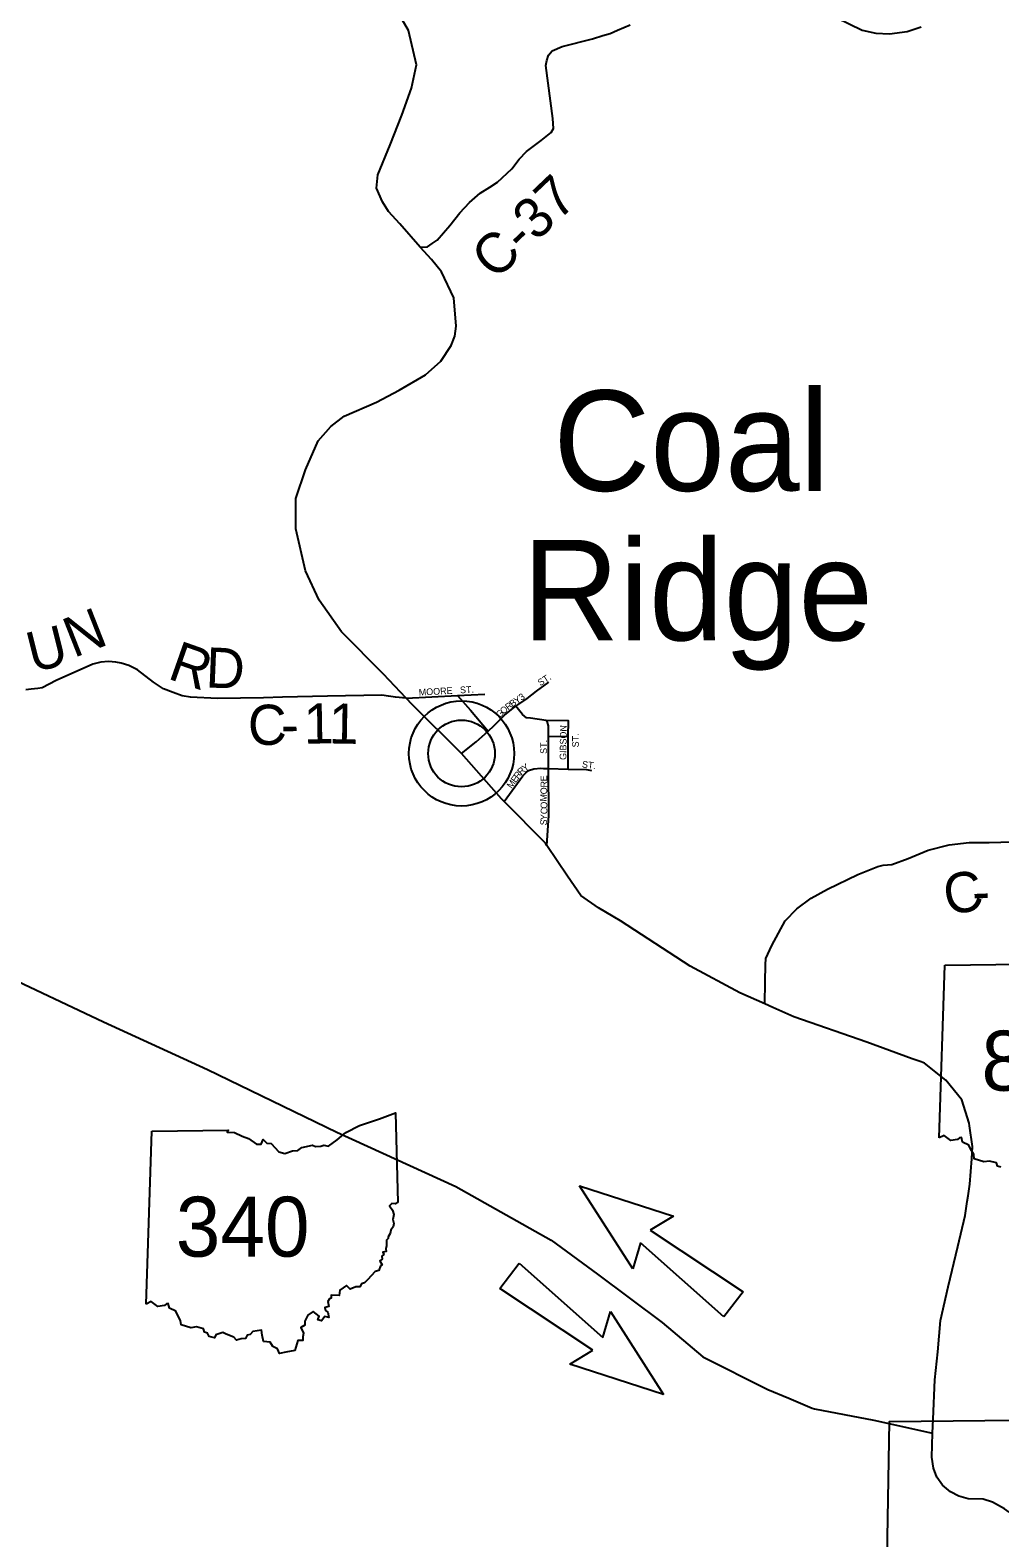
# Model space of a CAD drawing. Extents: x 0 to 34, y 0 to 22.
# Drawn here: x 24.277 to 25.646, y 11.032 to 13.16 of the extents above; entities that cross this region are included whole.
import ezdxf

# ---------------------------------------------------------------- set-up
doc = ezdxf.new("R2010")
doc.units = 0
for name, color, linetype in [('Default', 7, 'Continuous'), ('GM_X_Corporation', 7, 'Continuous'), ('GM_X_County_Road_Text', 7, 'Continuous'), ('GM_X_State_Route', 7, 'Continuous'), ('GM_X_Township_Subdivision', 7, 'Continuous'), ('GM_X_Township_Subdivision_Text', 7, 'Continuous'), ('GM_X_Unincorporated', 7, 'Continuous'), ('GM_X_Unincorporated_Text', 7, 'Continuous')]:
    doc.layers.add(name, color=color, linetype=linetype)

msp = doc.modelspace()

# ---------------------------------------------------------------- linework, layer by layer
at = {"layer": 'Default'}
for p, q in [((25.5601, 11.5962), (25.5679, 11.8402)), ((24.4408, 11.3618), (24.4487, 11.6058)), ((25.0526, 11.5286), (25.1849, 11.486)), ((25.1276, 11.4116), (25.0526, 11.5286)), ((25.1849, 11.486), (25.1523, 11.4661)), ((25.1523, 11.4661), (25.2836, 11.3789)), ((25.1386, 11.4483), (25.1276, 11.4116)), ((25.2563, 11.3436), (25.1386, 11.4483)), ((24.94, 11.3838), (24.9673, 11.4193)), ((24.9673, 11.4193), (25.0851, 11.3146)), ((25.0712, 11.2967), (24.94, 11.3838)), ((25.2836, 11.3789), (25.2563, 11.3436)), ((25.0851, 11.3146), (25.0959, 11.3511)), ((25.0959, 11.3511), (25.171, 11.2342)), ((25.0386, 11.2769), (25.0712, 11.2967)), ((25.171, 11.2342), (25.0386, 11.2769))]:
    msp.add_line(p, q, dxfattribs=at)
for points in [[(25.4145, 13.1777), (25.4515, 13.16), (25.4708, 13.1559), (25.4901, 13.1548), (25.5146, 13.1582), (25.5347, 13.1647)], [(24.8275, 12.8537), (24.8378, 12.8543), (24.8446, 12.8589), (24.8517, 12.8638), (24.8695, 12.8843), (24.8834, 12.9021), (24.897, 12.9169), (24.9121, 12.9298), (24.9257, 12.9385), (24.9367, 12.9453), (24.9567, 12.9643), (24.9673, 12.9779), (24.9775, 12.9886), (24.9982, 13.0045), (25.0122, 13.0155), (25.0156, 13.0212), (25.0148, 13.0352), (25.0049, 13.1101), (25.0061, 13.1173), (25.0087, 13.1245), (25.014, 13.131), (25.028, 13.137), (25.0706, 13.1477), (25.0854, 13.1523), (25.0956, 13.1553), (25.1062, 13.1599), (25.1239, 13.1675)], [(24.8078, 12.2172), (24.7929, 12.2187), (24.7827, 12.22), (24.7732, 12.2214), (24.6965, 12.22), (24.633, 12.2185), (24.6066, 12.2176), (24.5416, 12.2168), (24.5034, 12.2184), (24.4916, 12.2205), (24.4787, 12.2252), (24.4654, 12.2302), (24.4512, 12.2395), (24.4286, 12.2569), (24.4164, 12.2631), (24.4054, 12.2663), (24.3982, 12.2677), (24.3876, 12.269), (24.377, 12.2681), (24.3657, 12.2652), (24.3136, 12.2419), (24.2941, 12.2317), (24.2877, 12.2305), (24.2786, 12.2299), (24.2711, 12.2287)], [(25.3138, 11.7855), (25.3144, 11.8165), (25.3148, 11.8407), (25.3155, 11.8494), (25.3238, 11.868), (25.3427, 11.9028), (25.3593, 11.9199), (25.3793, 11.9347), (25.4024, 11.9476), (25.445, 11.9681), (25.4734, 11.9795), (25.4809, 11.9814), (25.493, 11.9822), (25.5164, 11.9909), (25.5444, 12.0023), (25.5742, 12.01), (25.6022, 12.0134), (25.6305, 12.0135), (25.6959, 12.0151)], [(25.5679, 11.8402), (25.6761, 11.8418)], [(24.2331, 11.8296), (24.3806, 11.7602), (24.5274, 11.6927), (24.7099, 11.6045), (24.8779, 11.5277), (25.0123, 11.4521), (25.078, 11.404), (25.1691, 11.3358), (25.2265, 11.2872), (25.3183, 11.241), (25.3479, 11.229), (25.3806, 11.2147), (25.3839, 11.2141), (25.4676, 11.1978), (25.5506, 11.1796)], [(24.4487, 11.6058), (24.5568, 11.6074), (24.5552, 11.6045), (24.5654, 11.6039), (24.5762, 11.5986), (24.5854, 11.5954), (24.5966, 11.5876), (24.6033, 11.5877), (24.6061, 11.5941), (24.6113, 11.5891), (24.6174, 11.5883), (24.628, 11.5766), (24.6367, 11.5741), (24.6471, 11.5781), (24.6548, 11.5787), (24.6606, 11.5827), (24.6754, 11.5861), (24.6796, 11.584), (24.6874, 11.5845), (24.6914, 11.5859), (24.6983, 11.5846), (24.7103, 11.5935), (24.7227, 11.6039), (24.7419, 11.6138), (24.7703, 11.6231), (24.7929, 11.6315), (24.7962, 11.5049)], [(25.6469, 11.5549), (25.6422, 11.5563), (25.6411, 11.5611), (25.631, 11.5637), (25.6232, 11.5627), (25.6096, 11.5666), (25.6087, 11.573), (25.6041, 11.5808), (25.6017, 11.5862), (25.5931, 11.5903), (25.5913, 11.5967), (25.5886, 11.5966), (25.586, 11.594), (25.5764, 11.5927), (25.5726, 11.5953), (25.5672, 11.5999), (25.5601, 11.5962)], [(24.7962, 11.5049), (24.7929, 11.5031), (24.7877, 11.5039), (24.7842, 11.5004), (24.7886, 11.4945), (24.7905, 11.4882), (24.7888, 11.4813), (24.7905, 11.4756), (24.7894, 11.4709), (24.7861, 11.4661), (24.785, 11.4616), (24.7822, 11.4568), (24.7824, 11.4541), (24.7798, 11.4521), (24.7802, 11.4441), (24.7789, 11.4398), (24.7794, 11.436), (24.775, 11.435), (24.776, 11.4319), (24.7733, 11.4294), (24.7739, 11.4253), (24.7708, 11.4226), (24.7738, 11.4173), (24.7714, 11.4156), (24.7694, 11.4091), (24.7639, 11.4078), (24.753, 11.3961), (24.749, 11.3916), (24.7447, 11.3905), (24.7423, 11.3859), (24.7369, 11.3859), (24.7287, 11.3827), (24.7235, 11.3881), (24.7143, 11.3816), (24.7132, 11.3739), (24.7017, 11.3742), (24.7021, 11.3703), (24.6995, 11.3692), (24.6971, 11.3654), (24.6985, 11.3585), (24.693, 11.3568), (24.6937, 11.3528), (24.6972, 11.3504), (24.6987, 11.3428), (24.693, 11.3443), (24.6882, 11.3379), (24.6833, 11.3394), (24.6849, 11.3448), (24.6767, 11.3514), (24.6689, 11.3462), (24.6648, 11.3378), (24.6647, 11.3321), (24.6589, 11.3288), (24.6627, 11.3208), (24.662, 11.3154), (24.6621, 11.3101), (24.6548, 11.3104), (24.6504, 11.2963)], [(24.6504, 11.2963), (24.6378, 11.2937), (24.6291, 11.2921), (24.626, 11.2984), (24.6197, 11.3018), (24.6156, 11.3082), (24.6066, 11.309), (24.6045, 11.3179), (24.6035, 11.325), (24.5912, 11.3232), (24.5878, 11.3189), (24.5834, 11.3177), (24.5809, 11.3133), (24.5749, 11.3129), (24.5685, 11.3108), (24.5644, 11.3151), (24.5539, 11.3195), (24.5492, 11.3217), (24.5393, 11.3183), (24.5373, 11.3141), (24.5295, 11.316), (24.5276, 11.3206), (24.5229, 11.3219), (24.5218, 11.3268), (24.5117, 11.3294), (24.5039, 11.3284), (24.4903, 11.3323), (24.4894, 11.3387), (24.4848, 11.3465), (24.4825, 11.3519), (24.4738, 11.3559), (24.472, 11.3624), (24.4693, 11.3622), (24.4668, 11.3596), (24.4571, 11.3584), (24.4533, 11.361), (24.4479, 11.3655), (24.4408, 11.3618)]]:
    msp.add_lwpolyline(points, dxfattribs=at)
at = {"layer": 'GM_X_Corporation'}
msp.add_lwpolyline([(25.9839, 11.2013), (25.9758, 10.8493), (26.0003, 10.8138), (26.0373, 10.7186), (26.1483, 10.7197), (26.1605, 10.702), (26.2388, 10.7027), (26.2375, 10.7269), (26.2453, 10.8102), (26.2937, 10.8129), (26.2856, 10.771), (26.2797, 10.7327), (26.2728, 10.7107), (26.268, 10.7008), (26.2431, 10.6885), (26.276, 10.5386), (26.0463, 10.4945), (25.9914, 10.6078), (25.7766, 10.4938), (25.6566, 10.4793), (25.5936, 10.5094), (25.478, 10.5119), (25.4897, 11.1961)], close=True, dxfattribs=at)
at = {"layer": 'GM_X_State_Route'}
for points in [[(25.5345, 11.7035), (25.522, 11.7081), (25.458, 11.7314), (25.3549, 11.7673), (25.3252, 11.7804), (25.3138, 11.7855), (25.2786, 11.801), (25.2084, 11.8386), (25.1101, 11.9029), (25.0794, 11.9209), (25.0543, 11.9383), (25.0353, 11.9658), (25.0064, 12.0093), (25.0044, 12.0123), (24.9462, 12.0712), (24.9424, 12.0749), (24.8859, 12.139), (24.8164, 12.2081), (24.8078, 12.2172), (24.7759, 12.2511), (24.7166, 12.3108), (24.685, 12.3553), (24.6655, 12.3966), (24.6521, 12.456), (24.6519, 12.4988), (24.6657, 12.5395), (24.6835, 12.5803), (24.7016, 12.6004), (24.7201, 12.6152), (24.7661, 12.6351), (24.7979, 12.6517), (24.8349, 12.6737), (24.8568, 12.6927), (24.8711, 12.7147), (24.8764, 12.7279), (24.8783, 12.7423), (24.8752, 12.7824), (24.8574, 12.8188), (24.8434, 12.8365), (24.8275, 12.8537), (24.7988, 12.8868), (24.7829, 12.9042), (24.7745, 12.9179), (24.7661, 12.9372), (24.7679, 12.9558), (24.7851, 12.9983), (24.8016, 13.0401), (24.8155, 13.0781), (24.8222, 13.1111), (24.811, 13.1596), (24.7927, 13.1909)], [(25.5997, 11.5067), (25.6009, 11.5144), (25.6034, 11.5312), (25.6063, 11.5669), (25.607, 11.5843), (25.6029, 11.6133), (25.6023, 11.6172), (25.592, 11.6502), (25.5695, 11.6777), (25.5391, 11.7018), (25.5345, 11.7035)], [(25.5514, 11.1991), (25.5538, 11.2547), (25.5581, 11.2941), (25.5618, 11.3385), (25.5729, 11.3863), (25.5863, 11.4428), (25.5968, 11.4868), (25.5997, 11.5067)], [(25.5506, 11.1796), (25.5506, 11.1796), (25.5514, 11.1991)], [(25.6587, 11.0681), (25.652, 11.0725), (25.6354, 11.082), (25.6223, 11.0864), (25.601, 11.087), (25.5876, 11.0908), (25.5759, 11.0968), (25.5648, 11.106), (25.5569, 11.1172), (25.5521, 11.1303), (25.5496, 11.1455), (25.5506, 11.1796)]]:
    msp.add_lwpolyline(points, dxfattribs=at)
at = {"layer": 'GM_X_Township_Subdivision'}
for points in [[(24.8859, 12.139), (24.9066, 12.1552), (24.9233, 12.1707), (24.9318, 12.1785), (24.9464, 12.193), (24.9562, 12.2011), (24.9626, 12.2057), (24.9652, 12.2076), (24.9787, 12.2168), (24.9915, 12.2271), (25.0092, 12.2397)], [(24.8078, 12.2172), (24.8801, 12.2208), (24.9186, 12.2227)], [(24.8801, 12.2208), (24.8987, 12.1999), (24.9233, 12.1707)], [(25.0064, 12.0093), (25.0091, 12.0512), (25.0088, 12.1178), (25.0086, 12.1623), (25.0085, 12.178), (25.0073, 12.1829), (25.0054, 12.1856), (24.9831, 12.1888), (24.9778, 12.1895), (24.9717, 12.194), (24.9626, 12.2057)], [(25.0362, 12.117), (25.0366, 12.1629), (25.0368, 12.1851), (25.0054, 12.1856)], [(25.0366, 12.1629), (25.0086, 12.1623)], [(24.9462, 12.0712), (24.9724, 12.1073), (24.9765, 12.1115), (24.9806, 12.1149), (24.9878, 12.1173), (24.998, 12.1181), (25.0016, 12.118)], [(25.0016, 12.118), (25.0018, 12.118), (25.0088, 12.1178), (25.0362, 12.117), (25.0623, 12.1163), (25.0691, 12.1149)]]:
    msp.add_lwpolyline(points, dxfattribs=at)
at = {"layer": 'GM_X_Unincorporated'}
for radius in [0.0742, 0.0471]:
    msp.add_circle((24.8859, 12.139), radius, dxfattribs=at)

# ---------------------------------------------------------------- texts
at = {"layer": 'Default'}
for s, p in [('821', (25.6197, 11.663)), ('340', (24.4826, 11.4287))]:
    msp.add_text(s, height=0.08462, dxfattribs=at).set_placement(p)
at = {"layer": 'GM_X_County_Road_Text'}
for s, rotation, p in [('C-37', 43.571, (24.9336, 12.8056)), ('N', 21.4478, (24.3385, 12.2735)), ('U', 14.0943, (24.2807, 12.2529)), ('R', 340.5848, (24.4694, 12.2453)), ('D', 357.6355, (24.5241, 12.2323)), ('C', 1.0226, (24.5849, 12.1506)), ('1', 0.9263, (24.6637, 12.1527)), ('1', 359.0164, (24.6981, 12.1532)), ('-', 0.9992, (24.6315, 12.1515)), ('C', 9.2948, (25.571, 11.9106)), ('-', 2.1939, (25.6074, 11.9155))]:
    msp.add_text(s, height=0.0567, rotation=rotation, dxfattribs=at).set_placement(p)
at = {"layer": 'GM_X_Township_Subdivision_Text'}
for s, rotation, p in [('ST.', 32.7431, (24.997, 12.2338)), ('MOORE   ST.', 3.1678, (24.8258, 12.2206)), ('Y', 34.8541, (24.9638, 12.2083)), ('3', 34.9503, (24.9706, 12.2131)), ('G', 47.0868, (24.94, 12.1885)), ('O', 38.8373, (24.9448, 12.1937)), ('R', 36.6076, (24.9518, 12.1995)), ('B', 36.0684, (24.9578, 12.204)), ('GIBSON', 89.2834, (25.0338, 12.1298)), ('ST.', 90, (25.0065, 12.1384)), ('ST.', 90, (25.0514, 12.1476)), ('R', 54.3494, (24.9662, 12.1022)), ('R', 45.2232, (24.9703, 12.108)), ('Y', 34.2114, (24.9752, 12.113)), ('ST.', 352.865, (25.0554, 12.1193)), ('M', 54.4708, (24.9566, 12.0887)), ('E', 54.4734, (24.9624, 12.0968)), ('O', 89.4861, (25.0067, 12.0813)), ('E', 89.9956, (25.0068, 12.0996)), ('R', 89.994, (25.0069, 12.091)), ('M', 86.6464, (25.0061, 12.0709)), ('O', 86.6374, (25.0066, 12.0608)), ('Y', 86.6374, (25.0065, 12.0445)), ('C', 86.5979, (25.0068, 12.053)), ('S', 86.6111, (25.0062, 12.0373))]:
    msp.add_text(s, height=0.00945, rotation=rotation, dxfattribs=at).set_placement(p)
at = {"layer": 'GM_X_Unincorporated_Text'}
for s, p in [('Coal', (25.0154, 12.5097)), ('Ridge', (24.9715, 12.2987))]:
    msp.add_text(s, height=0.14175, rotation=0, dxfattribs=at).set_placement(p)

doc.saveas('drawing.dxf')
